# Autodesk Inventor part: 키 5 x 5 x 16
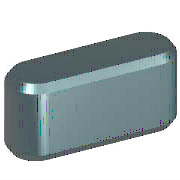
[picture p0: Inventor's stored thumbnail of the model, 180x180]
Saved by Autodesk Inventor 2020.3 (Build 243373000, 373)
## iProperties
Created: 2012-02
Part Number: 키 5 x 5 x 16
Material: 강철, 연강
Description: 키 및 해당 키홈
Document SubType Name: Modeling
Standard: KS B 1311
Designer: mduedu
Standards Organization: KS
Language: ko-KR
Size Designation: 5 x 5 x 16
Categories: <MemberInstance><Categories><Category DisplayName="샤프트 부품" InternalName="7f7aeb1f-a693-4053-b835-cee3144e0d98" Mnemonic="SHFT"><Category DisplayName="키" Interna
Density: 1 g/cm^3
Appearance: 노란색
IsCustomPart: 1
Author: mduedu
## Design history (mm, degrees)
workplane "Work Plane1"
workplane "Work Plane2"
sketch "스케치1"
  geometry: L1 (2.5, 2.5)-(13.5, 2.5); L2 (13.5, -2.5)-(2.5, -2.5); L3 (0, 9.4)-(0, -7.4) reference; L4 (-5, 0)-(30, 0) reference; L5 (16, 0)-(16, 7); A1 r 2.5 centre (2.5, 0) between (2.5, 2.5) and (2.5, -2.5); A2 r 2.5 centre (13.5, 0) between (13.5, -2.5) and (13.5, 2.5)
  constraints: 6 end point, 5 point on circle, 4 tangent, 3 point on line, 2 centre point, 1 horizontal, 1 parallel, 1 perpendicular
  dimensions: "d0" = 2.5 radius of A1 (= 0.5 x PB); "d13" = 2.5 radius of A2 (= 0.5 x PB); "d14" = 16 distance between parallel lines of L5 L3 (= NLG)
extrude "본체1" new body sketch "스케치1" taper "d3" = 0 deg; stored distance "d4" = 10
workplane "Work Plane3"
body "Solid1"
chamfer "모따기1" distance "d8" = 0.4 (= PHH); stored, may be unused: second distance "d9" = 0.4 (= PHH), angle "d15" = 45 deg
other parameters: "d1" = -3 (= -PNT), "d2" = 2 (= PH - PNT), "NLG" = 16 [user parameter; used in 3 equation terms], "PB" = 5 [user parameter; used in 2 equation terms], "PNT" = 3 [user parameter; used in 2 equation terms], "PH" = 5 [user parameter; used in 1 equation term], "PHH" = 0.4 [user parameter; used in 2 equation terms], "d10" = 0, "d16" = 0, "d17" = 0, "d18" = 0, "WDMIN" = 12 [user parameter], "PLB2" = 16 (= NLG) [user parameter], "WDMAX" = 17 [user parameter], "PLB1" = 16 (= NLG) [user parameter], "RR" = 0.16 [user parameter], "PUEB" = 2.3 [user parameter]
